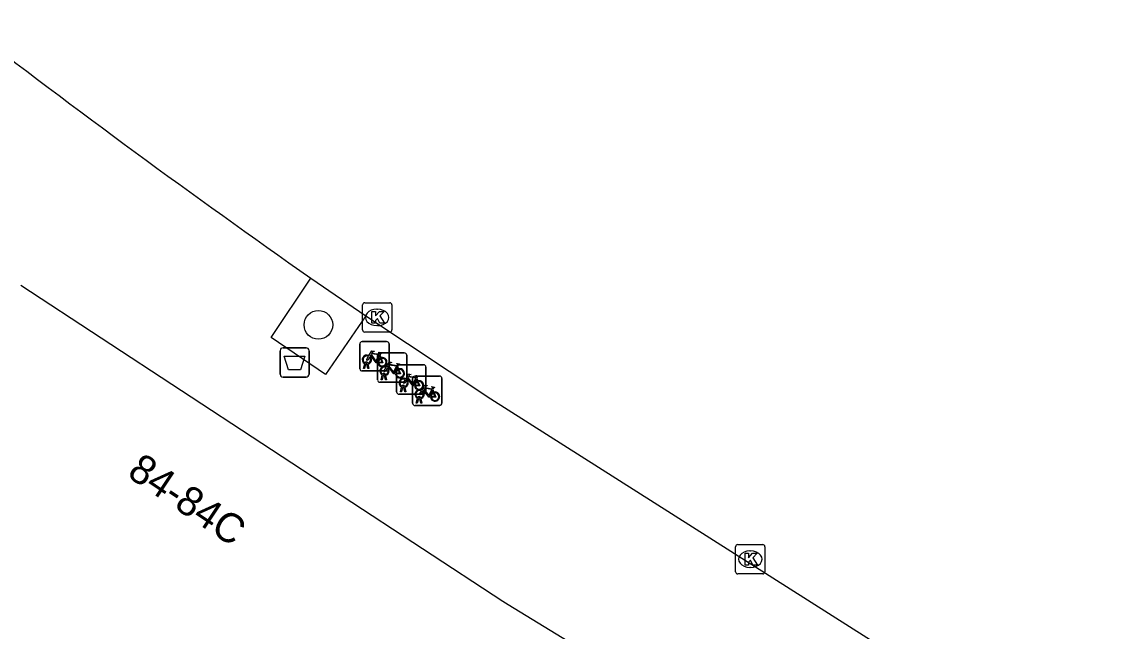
# Model space of a CAD drawing. Extents: x 161801 to 162379, y 382315 to 382832.
# Drawn here: x 162087.53 to 162125.06, y 382676.21 to 382696.99 of the extents above; entities that cross this region are included whole.
import ezdxf

# ---------------------------------------------------------------- set-up
doc = ezdxf.new("R2010")
doc.units = 0
for name, color, linetype in [('IMGEO_Afvalbak', 7, 'Continuous'), ('IMGEO_Boom', 7, 'Continuous'), ('IMGEO_Fietsenrek', 7, 'Continuous'), ('IMGEO_Kolk', 7, 'Continuous'), ('IMGEO_Pand', 7, 'Continuous'), ('IMGEO_Pand_nummerreeks', 7, 'Continuous'), ('IMGEO_Rijbaan_lokaal_open', 7, 'Continuous'), ('IMGEO_Voetpad_open', 7, 'Continuous')]:
    doc.layers.add(name, color=color, linetype=linetype)

msp = doc.modelspace()

# ---------------------------------------------------------------- linework, layer by layer
at = {"layer": 'IMGEO_Afvalbak'}
for p, q in [((162096.343, 382684.978), (162096.343, 382685.778)), ((162096.343, 382685.778), (162096.343, 382684.978)), ((162096.443, 382685.878), (162097.233, 382685.878)), ((162097.233, 382685.878), (162096.443, 382685.878)), ((162097.333, 382685.778), (162097.333, 382684.978)), ((162097.333, 382684.978), (162097.333, 382685.778)), ((162097.233, 382684.878), (162096.443, 382684.878)), ((162096.443, 382684.878), (162097.233, 382684.878))]:
    msp.add_line(p, q, dxfattribs=at)
msp.add_lwpolyline([(162096.486, 382685.592), (162097.19, 382685.592), (162097.041, 382685.122), (162096.635, 382685.122), (162096.486, 382685.592)], dxfattribs=at)
for centre, start, end in [((162096.443, 382685.778), 90, 180), ((162096.443, 382685.778), 90, 180), ((162097.233, 382685.778), 0, 90), ((162097.233, 382685.778), 360, 90), ((162096.443, 382684.978), 180, 270), ((162096.443, 382684.978), 180, 270), ((162097.233, 382684.978), 270, 0), ((162097.233, 382684.978), 270, 0)]:
    msp.add_arc(centre, 0.1, start, end, dxfattribs=at)
at = {"layer": 'IMGEO_Boom'}
msp.add_circle((162097.65, 382686.66), 0.489, dxfattribs=at)
at = {"layer": 'IMGEO_Fietsenrek'}
for p, q in [((162099.14, 382686.088), (162099.981, 382686.088)), ((162099.981, 382686.088), (162099.14, 382686.088)), ((162099.065, 382685.163), (162099.065, 382686.004)), ((162099.065, 382686.004), (162099.065, 382685.163)), ((162099.742, 382685.704), (162100.583, 382685.704)), ((162100.583, 382685.704), (162099.742, 382685.704)), ((162100.065, 382686.013), (162100.065, 382685.172)), ((162100.065, 382685.172), (162100.065, 382686.013)), ((162099.192, 382685.172), (162099.231, 382685.332)), ((162099.261, 382685.32), (162099.226, 382685.172)), ((162099.303, 382685.344), (162099.302, 382685.348)), ((162099.344, 382685.172), (162099.31, 382685.314)), ((162099.334, 382685.355), (162099.335, 382685.348)), ((162099.342, 382685.318), (162099.377, 382685.172)), ((162099.667, 382684.779), (162099.667, 382685.62)), ((162099.667, 382685.62), (162099.667, 382684.779)), ((162099.752, 382685.637), (162099.788, 382685.542)), ((162100.397, 382685.296), (162101.238, 382685.296)), ((162101.238, 382685.296), (162100.397, 382685.296)), ((162100.667, 382685.629), (162100.667, 382684.788)), ((162100.667, 382684.788), (162100.667, 382685.629)), ((162099.99, 382685.088), (162099.149, 382685.088)), ((162099.149, 382685.088), (162099.99, 382685.088)), ((162099.226, 382685.172), (162099.192, 382685.172)), ((162099.377, 382685.172), (162099.344, 382685.172)), ((162099.794, 382684.788), (162099.833, 382684.948)), ((162099.863, 382684.936), (162099.828, 382684.788)), ((162099.905, 382684.96), (162099.904, 382684.964)), ((162099.946, 382684.788), (162099.912, 382684.93)), ((162099.936, 382684.971), (162099.937, 382684.964)), ((162099.944, 382684.934), (162099.979, 382684.788)), ((162100.322, 382684.371), (162100.322, 382685.212)), ((162100.322, 382685.212), (162100.322, 382684.371)), ((162100.354, 382685.253), (162100.39, 382685.158)), ((162100.943, 382684.91), (162101.784, 382684.91)), ((162101.784, 382684.91), (162100.943, 382684.91)), ((162101.322, 382685.221), (162101.322, 382684.38)), ((162101.322, 382684.38), (162101.322, 382685.221)), ((162100.592, 382684.704), (162099.751, 382684.704)), ((162099.751, 382684.704), (162100.592, 382684.704)), ((162099.828, 382684.788), (162099.794, 382684.788)), ((162099.979, 382684.788), (162099.946, 382684.788)), ((162100.449, 382684.38), (162100.488, 382684.54)), ((162100.56, 382684.552), (162100.559, 382684.556)), ((162100.591, 382684.563), (162100.592, 382684.556)), ((162100.868, 382683.985), (162100.868, 382684.826)), ((162100.868, 382684.826), (162100.868, 382683.985)), ((162101.009, 382684.845), (162101.045, 382684.75)), ((162101.868, 382684.835), (162101.868, 382683.994)), ((162101.868, 382683.994), (162101.868, 382684.835)), ((162101.247, 382684.296), (162100.406, 382684.296)), ((162100.406, 382684.296), (162101.247, 382684.296)), ((162100.483, 382684.38), (162100.449, 382684.38)), ((162100.518, 382684.528), (162100.483, 382684.38)), ((162100.601, 382684.38), (162100.567, 382684.522)), ((162100.599, 382684.526), (162100.634, 382684.38)), ((162100.634, 382684.38), (162100.601, 382684.38)), ((162100.995, 382683.994), (162101.034, 382684.154)), ((162101.106, 382684.166), (162101.105, 382684.17)), ((162101.137, 382684.177), (162101.138, 382684.17)), ((162101.555, 382684.459), (162101.591, 382684.364)), ((162101.793, 382683.91), (162100.952, 382683.91)), ((162100.952, 382683.91), (162101.793, 382683.91)), ((162101.029, 382683.994), (162100.995, 382683.994)), ((162101.064, 382684.142), (162101.029, 382683.994)), ((162101.147, 382683.994), (162101.113, 382684.136)), ((162101.145, 382684.14), (162101.18, 382683.994)), ((162101.18, 382683.994), (162101.147, 382683.994))]:
    msp.add_line(p, q, dxfattribs=at)
for points in [[(162099.378, 382685.614), (162099.473, 382685.778), (162099.559, 382685.764), (162099.561, 382685.755), (162099.505, 382685.744), (162099.478, 382685.699), (162099.734, 382685.658)], [(162099.721, 382685.633), (162099.464, 382685.674), (162099.447, 382685.645), (162099.614, 382685.425), (162099.721, 382685.633)], [(162099.734, 382685.658), (162099.759, 382685.707), (162099.753, 382685.711), (162099.73, 382685.715), (162099.718, 382685.722), (162099.717, 382685.725), (162099.719, 382685.73), (162099.814, 382685.715), (162099.816, 382685.705), (162099.806, 382685.692), (162099.794, 382685.686), (162099.78, 382685.692), (162099.752, 382685.637)], [(162099.399, 382685.562), (162099.347, 382685.472), (162099.307, 382685.447), (162099.308, 382685.494), (162099.363, 382685.588)], [(162099.674, 382685.37), (162099.624, 382685.37), (162099.433, 382685.621), (162099.414, 382685.589)], [(162099.769, 382685.535), (162099.739, 382685.612), (162099.63, 382685.394), (162099.673, 382685.394)], [(162099.703, 382685.394), (162099.823, 382685.393), (162099.779, 382685.507)], [(162099.799, 382685.514), (162099.854, 382685.369), (162099.704, 382685.369)], [(162099.98, 382685.23), (162100.075, 382685.394), (162100.161, 382685.38), (162100.163, 382685.371), (162100.107, 382685.36), (162100.08, 382685.315), (162100.336, 382685.274)], [(162100.323, 382685.249), (162100.066, 382685.29), (162100.049, 382685.261), (162100.216, 382685.041), (162100.323, 382685.249)], [(162100.336, 382685.274), (162100.361, 382685.323), (162100.355, 382685.327), (162100.332, 382685.331), (162100.32, 382685.338), (162100.319, 382685.341), (162100.321, 382685.346), (162100.416, 382685.331), (162100.418, 382685.321), (162100.408, 382685.308), (162100.396, 382685.302), (162100.382, 382685.308), (162100.354, 382685.253)], [(162100.001, 382685.178), (162099.949, 382685.088), (162099.909, 382685.063), (162099.91, 382685.11), (162099.965, 382685.204)], [(162100.276, 382684.986), (162100.226, 382684.986), (162100.035, 382685.237), (162100.016, 382685.205)], [(162100.371, 382685.151), (162100.341, 382685.228), (162100.232, 382685.01), (162100.275, 382685.01)], [(162100.305, 382685.01), (162100.425, 382685.009), (162100.381, 382685.123)], [(162100.401, 382685.13), (162100.456, 382684.985), (162100.306, 382684.985)], [(162100.635, 382684.822), (162100.73, 382684.986), (162100.816, 382684.972), (162100.818, 382684.963), (162100.762, 382684.952), (162100.735, 382684.907), (162100.991, 382684.866)], [(162100.991, 382684.866), (162101.016, 382684.915), (162101.01, 382684.919), (162100.987, 382684.923), (162100.975, 382684.93), (162100.974, 382684.933), (162100.976, 382684.938), (162101.071, 382684.923), (162101.073, 382684.913), (162101.063, 382684.9), (162101.051, 382684.894), (162101.037, 382684.9), (162101.009, 382684.845)], [(162100.656, 382684.77), (162100.604, 382684.68), (162100.564, 382684.655), (162100.565, 382684.702), (162100.62, 382684.796)], [(162100.931, 382684.578), (162100.881, 382684.578), (162100.69, 382684.829), (162100.671, 382684.797)], [(162100.978, 382684.841), (162100.721, 382684.882), (162100.704, 382684.853), (162100.871, 382684.633), (162100.978, 382684.841)], [(162101.026, 382684.743), (162100.996, 382684.82), (162100.887, 382684.602), (162100.93, 382684.602)], [(162100.96, 382684.602), (162101.08, 382684.601), (162101.036, 382684.715)], [(162101.056, 382684.722), (162101.111, 382684.577), (162100.961, 382684.577)], [(162101.181, 382684.436), (162101.276, 382684.6), (162101.362, 382684.586), (162101.364, 382684.577), (162101.308, 382684.566), (162101.281, 382684.521), (162101.537, 382684.48)], [(162101.537, 382684.48), (162101.562, 382684.529), (162101.556, 382684.533), (162101.533, 382684.537), (162101.521, 382684.544), (162101.52, 382684.547), (162101.522, 382684.552), (162101.617, 382684.537), (162101.619, 382684.527), (162101.609, 382684.514), (162101.597, 382684.508), (162101.583, 382684.514), (162101.555, 382684.459)], [(162101.202, 382684.384), (162101.15, 382684.294), (162101.11, 382684.269), (162101.111, 382684.316), (162101.166, 382684.41)], [(162101.477, 382684.192), (162101.427, 382684.192), (162101.236, 382684.443), (162101.217, 382684.411)], [(162101.524, 382684.455), (162101.267, 382684.496), (162101.25, 382684.467), (162101.417, 382684.247), (162101.524, 382684.455)], [(162101.572, 382684.357), (162101.542, 382684.434), (162101.433, 382684.216), (162101.476, 382684.216)], [(162101.506, 382684.216), (162101.626, 382684.215), (162101.582, 382684.329)], [(162101.602, 382684.336), (162101.657, 382684.191), (162101.507, 382684.191)]]:
    msp.add_lwpolyline(points, dxfattribs=at)
for centre, radius, start, end in [((162099.143, 382686.01), 0.0779, 92.4484, 184.2845), ((162099.143, 382686.01), 0.0779, 92.4484, 184.2845), ((162099.987, 382686.01), 0.0779, 2.4484, 94.2845), ((162099.987, 382686.01), 0.0779, 2.4484, 94.2845), ((162099.745, 382685.626), 0.0779, 92.4484, 184.2845), ((162099.745, 382685.626), 0.0779, 92.4484, 184.2845), ((162100.589, 382685.626), 0.0779, 2.4484, 94.2845), ((162100.589, 382685.626), 0.0779, 2.4484, 94.2845), ((162099.305, 382685.473), 0.159, 62.6766, 242.1369), ((162099.305, 382685.473), 0.129, 63.3192, 238.903), ((162099.285, 382685.344), 0.0499, 12.8025, 158.6934), ((162099.305, 382685.473), 0.159, 253.9967, 271.7867), ((162099.285, 382685.344), 0.0174, 12.8025, 163.4502), ((162099.305, 382685.473), 0.129, 253.415, 269.0204), ((162099.305, 382685.473), 0.129, 283.6043, 43.4302), ((162099.305, 382685.473), 0.159, 283.5766, 46.6042), ((162099.832, 382685.389), 0.159, 113.3408, 178.3217), ((162099.832, 382685.389), 0.159, 187.0065, 105.7708), ((162099.832, 382685.389), 0.129, 113.923, 177.9556), ((162099.832, 382685.389), 0.129, 188.6715, 104.5883), ((162100.4, 382685.218), 0.0779, 92.4484, 184.2845), ((162100.4, 382685.218), 0.0779, 92.4484, 184.2845), ((162101.244, 382685.218), 0.0779, 2.4484, 94.2845), ((162101.244, 382685.218), 0.0779, 2.4484, 94.2845), ((162099.143, 382685.166), 0.0779, 182.4484, 274.2845), ((162099.143, 382685.166), 0.0779, 182.4484, 274.2845), ((162099.907, 382685.089), 0.159, 62.6766, 242.1369), ((162099.907, 382685.089), 0.129, 63.3192, 238.903), ((162099.887, 382684.96), 0.0499, 12.8025, 158.6934), ((162099.907, 382685.089), 0.159, 253.9967, 271.7867), ((162099.887, 382684.96), 0.0174, 12.8025, 163.4502), ((162099.907, 382685.089), 0.129, 253.415, 269.0204), ((162099.907, 382685.089), 0.129, 283.6043, 43.4302), ((162099.907, 382685.089), 0.159, 283.5766, 46.6042), ((162099.987, 382685.166), 0.0779, 272.4484, 4.2845), ((162099.987, 382685.166), 0.0779, 272.4484, 4.2845), ((162100.434, 382685.005), 0.159, 113.3408, 178.3217), ((162100.434, 382685.005), 0.159, 187.0065, 105.7708), ((162100.434, 382685.005), 0.129, 113.923, 177.9556), ((162100.434, 382685.005), 0.129, 188.6715, 104.5883), ((162100.946, 382684.832), 0.0779, 92.4484, 184.2845), ((162100.946, 382684.832), 0.0779, 92.4484, 184.2845), ((162101.79, 382684.832), 0.0779, 2.4484, 94.2845), ((162101.79, 382684.832), 0.0779, 2.4484, 94.2845), ((162099.745, 382684.782), 0.0779, 182.4484, 274.2845), ((162099.745, 382684.782), 0.0779, 182.4484, 274.2845), ((162100.562, 382684.681), 0.159, 62.6766, 242.1369), ((162100.562, 382684.681), 0.129, 63.3192, 238.903), ((162100.542, 382684.552), 0.0499, 12.8025, 158.6934), ((162100.542, 382684.552), 0.0174, 12.8025, 163.4502), ((162100.562, 382684.681), 0.129, 253.415, 269.0204), ((162100.589, 382684.782), 0.0779, 272.4484, 4.2845), ((162100.589, 382684.782), 0.0779, 272.4484, 4.2845), ((162100.562, 382684.681), 0.129, 283.6043, 43.4302), ((162100.562, 382684.681), 0.159, 283.5766, 46.6042), ((162101.089, 382684.597), 0.159, 113.3408, 178.3217), ((162101.089, 382684.597), 0.159, 187.0065, 105.7708), ((162101.089, 382684.597), 0.129, 113.923, 177.9556), ((162101.089, 382684.597), 0.129, 188.6715, 104.5883), ((162100.4, 382684.374), 0.0779, 182.4484, 274.2845), ((162100.4, 382684.374), 0.0779, 182.4484, 274.2845), ((162100.562, 382684.681), 0.159, 253.9967, 271.7867), ((162101.108, 382684.295), 0.159, 62.6766, 242.1369), ((162101.108, 382684.295), 0.129, 63.3192, 238.903), ((162101.088, 382684.166), 0.0499, 12.8025, 158.6934), ((162101.088, 382684.166), 0.0174, 12.8025, 163.4502), ((162101.108, 382684.295), 0.129, 253.415, 269.0204), ((162101.108, 382684.295), 0.129, 283.6043, 43.4302), ((162101.108, 382684.295), 0.159, 283.5766, 46.6042), ((162101.244, 382684.374), 0.0779, 272.4484, 4.2845), ((162101.244, 382684.374), 0.0779, 272.4484, 4.2845), ((162101.635, 382684.211), 0.159, 113.3408, 178.3217), ((162101.635, 382684.211), 0.159, 187.0065, 105.7708), ((162101.635, 382684.211), 0.129, 113.923, 177.9556), ((162101.635, 382684.211), 0.129, 188.6715, 104.5883), ((162100.946, 382683.988), 0.0779, 182.4484, 274.2845), ((162100.946, 382683.988), 0.0779, 182.4484, 274.2845), ((162101.108, 382684.295), 0.159, 253.9967, 271.7867), ((162101.79, 382683.988), 0.0779, 272.4484, 4.2845), ((162101.79, 382683.988), 0.0779, 272.4484, 4.2845)]:
    msp.add_arc(centre, radius, start, end, dxfattribs=at)
at = {"layer": 'IMGEO_Kolk'}
for p, q in [((162099.159, 382686.488), (162099.159, 382687.34)), ((162099.234, 382687.414), (162100.086, 382687.414)), ((162099.647, 382687.194), (162099.672, 382687.194)), ((162100.16, 382687.34), (162100.16, 382686.488)), ((162100.086, 382686.414), (162099.234, 382686.414)), ((162099.67, 382686.634), (162099.645, 382686.634)), ((162111.899, 382678.239), (162111.899, 382679.091)), ((162111.974, 382679.165), (162112.826, 382679.165)), ((162112.387, 382678.945), (162112.412, 382678.945)), ((162112.9, 382679.091), (162112.9, 382678.239)), ((162112.826, 382678.165), (162111.974, 382678.165)), ((162112.41, 382678.385), (162112.385, 382678.385))]:
    msp.add_line(p, q, dxfattribs=at)
for points in [[(162099.159, 382686.488), (162099.159, 382687.34)], [(162099.234, 382687.414), (162100.086, 382687.414)], [(162100.16, 382687.34), (162100.16, 382686.488)], [(162099.48, 382687.114), (162099.603, 382687.114), (162099.603, 382686.963), (162099.733, 382687.114), (162099.897, 382687.114), (162099.751, 382686.963), (162099.904, 382686.714), (162099.752, 382686.714), (162099.667, 382686.878), (162099.603, 382686.811), (162099.603, 382686.714), (162099.48, 382686.714), (162099.48, 382687.114)], [(162100.086, 382686.414), (162099.234, 382686.414)], [(162111.899, 382678.239), (162111.899, 382679.091)], [(162111.974, 382679.165), (162112.826, 382679.165)], [(162112.9, 382679.091), (162112.9, 382678.239)], [(162112.22, 382678.865), (162112.343, 382678.865), (162112.343, 382678.714), (162112.473, 382678.865), (162112.637, 382678.865), (162112.491, 382678.714), (162112.644, 382678.465), (162112.492, 382678.465), (162112.407, 382678.629), (162112.343, 382678.562), (162112.343, 382678.465), (162112.22, 382678.465), (162112.22, 382678.865)], [(162112.826, 382678.165), (162111.974, 382678.165)]]:
    msp.add_lwpolyline(points, dxfattribs=at)
for centre, start, end in [((162099.236, 382687.338), 91.552, 178.448), ((162099.236, 382687.338), 91.552, 178.448), ((162100.084, 382687.338), 1.552, 88.448), ((162100.084, 382687.338), 1.552, 88.448), ((162099.236, 382686.49), 181.552, 268.448), ((162099.236, 382686.49), 181.552, 268.448), ((162100.084, 382686.49), 271.552, 358.448), ((162100.084, 382686.49), 271.552, 358.448), ((162111.976, 382679.089), 91.552, 178.448), ((162111.976, 382679.089), 91.552, 178.448), ((162112.824, 382679.089), 1.552, 88.448), ((162112.824, 382679.089), 1.552, 88.448), ((162111.976, 382678.241), 181.552, 268.448), ((162111.976, 382678.241), 181.552, 268.448), ((162112.824, 382678.241), 271.552, 358.448), ((162112.824, 382678.241), 271.552, 358.448)]:
    msp.add_arc(centre, 0.0765, start, end, dxfattribs=at)
for centre, major_axis, ratio, start_param, end_param in [((162099.646, 382686.914), (-0.387, 0.002), 0.722429, 4.712389, 7.853982), ((162099.671, 382686.914), (-0.39, 0.002), 0.717154, 1.570796, 4.712389), ((162112.386, 382678.665), (-0.387, 0.002), 0.722429, 4.712389, 7.853982), ((162112.411, 382678.665), (-0.39, 0.002), 0.717154, 1.570796, 4.712389)]:
    msp.add_ellipse(centre, major_axis=major_axis, ratio=ratio, start_param=start_param, end_param=end_param, dxfattribs=at)
at = {"layer": 'IMGEO_Pand'}
msp.add_lwpolyline([(162087.494, 382688.013), (162103.949, 382677.238), (162104.136, 382677.116), (162106.594, 382675.618)], dxfattribs=at)
at = {"layer": 'IMGEO_Rijbaan_lokaal_open'}
for points in [[(162097.396, 382688.25), (162099.27, 382686.974)], [(162099.27, 382686.974), (162103.542, 382684.136), (162109.115, 382680.594), (162117.092, 382675.543), (162129.893, 382667.475), (162130.048, 382667.707)]]:
    msp.add_lwpolyline(points, dxfattribs=at)
msp.add_arc((162287.694, 382959.98), 331.738, 232.4433, 234.99566, dxfattribs=at)
at = {"layer": 'IMGEO_Voetpad_open'}
msp.add_lwpolyline([(162099.27, 382686.974), (162097.898, 382684.971), (162096.036, 382686.226), (162097.396, 382688.25)], dxfattribs=at)

# ---------------------------------------------------------------- texts
at = {"layer": 'IMGEO_Pand_nummerreeks'}
msp.add_text('84-84C', height=1, rotation=326.2929, dxfattribs=at).set_placement((162091.078, 382681.505))

doc.saveas('drawing.dxf')
